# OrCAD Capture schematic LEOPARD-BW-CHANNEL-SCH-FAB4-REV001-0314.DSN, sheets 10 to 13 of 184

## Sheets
10 169_P1V05_PCH_TPS53318: size C; title: P1V05_PCH_TPS53318
11 168_PVCCIO_TPS53511: size A3; title: PVCCIO_TPS53511
12 167_PVPP_GH_TPS53318: size A3; title: PVPP_GH_TPS53318
13 166_PVDDQ_GH_Decoupling: size A3; title: PVDDQ_GH_DECOUPLING

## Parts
sheet 166_PVDDQ_GH_Decoupling
PC675  SCD1U25V3KX-GP  [C603H36]
PC676  SC1U25V3KX-GP  [C603H36]
PC677  SCD1U25V5KX-1GP  [C805H54]
PC678  SE470UF2VDM-GP  [CT7343H83]
PC679  SE470UF2VDM-GP  [CT7343H83]
PC680  SE470UF2VDM-GP  [CT7343H83]
PC681  SE470UF2VDM-GP  [CT7343H83]
PC682  SC47U4V5MX-2-GP  [C805H58]
PC683  SC47U4V5MX-2-GP  [C805H58]
PC684  SC47U4V5MX-2-GP  [C805H58]
PC685  SC47U4V5MX-2-GP  [C805H58]
PC686  SC22U6D3V5MX-5-GP  [C805H56]
PC687  SC22U6D3V5MX-5-GP  [C805H56]
PC688  SC22U6D3V5MX-5-GP  [C805H56]
PC689  SC22U6D3V5MX-5-GP  [C805H56]
PC690  SC22U6D3V5MX-5-GP  [C805H56]
PC691  SC22U6D3V5MX-5-GP  [C805H56]
PC692  SC22U6D3V5MX-5-GP  [C805H56]
PC693  SC22U6D3V5MX-5-GP  [C805H56]
PC694  SC22U6D3V5MX-5-GP  [C805H56]
PC695  SC22U6D3V5MX-5-GP  [C805H56]
PC696  SC22U6D3V5MX-5-GP  [C805H56]
PC697  SC22U6D3V5MX-5-GP  [C805H56]
PC698  SC22U6D3V5MX-5-GP  [C805H56]
PC699  SC22U6D3V5MX-5-GP  [C805H56]
PC700  SC22U6D3V5MX-5-GP  [C805H56]
PC701  SC22U6D3V5MX-5-GP  [C805H56]
PC702  SC22U6D3V5MX-5-GP  [C805H56]
PC703  SC22U6D3V5MX-5-GP  [C805H56]
PC704  SC22U6D3V5MX-5-GP  [C805H56]
PC705  SC22U6D3V5MX-5-GP  [C805H56]
PC706  SC22U6D3V5MX-5-GP  [C805H56]
PC707  SC22U6D3V5MX-5-GP  [C805H56]
PC708  SC22U6D3V5MX-5-GP  [C805H56]
PC709  SC22U6D3V5MX-5-GP  [C805H56]
PC710  SC22U6D3V5MX-5-GP  [C805H56]
PC711  SC22U6D3V5MX-5-GP  [C805H56]
PC712  SC22U6D3V5MX-5-GP  [C805H56]
PC713  SC22U6D3V5MX-5-GP  [C805H56]
PC714  SC22U6D3V5MX-5-GP  [C805H56]
PC715  SC22U6D3V5MX-5-GP  [C805H56]
PC716  SC22U6D3V5MX-5-GP  [C805H56]
PC717  SC22U6D3V5MX-5-GP  [C805H56]
PC718  SC22U6D3V5MX-5-GP  [C805H56]
PC719  SC22U6D3V5MX-5-GP  [C805H56]
PC720  SC22U6D3V5MX-5-GP  [C805H56]
PC721  SC22U6D3V5MX-5-GP  [C805H56]
PC722  SC22U6D3V5MX-5-GP  [C805H56]
PC723  SC22U6D3V5MX-5-GP  [C805H56]
PC724  SC22U6D3V5MX-5-GP  [C805H56]
PC725  SC22U6D3V5MX-5-GP  [C805H56]
PC865  SC22U6D3V5MX-5-GP  [C805H56]
PC866  SC22U6D3V5MX-5-GP  [C805H56]
PC867  SC22U6D3V5MX-5-GP  [C805H56]
PC868  SC22U6D3V5MX-5-GP  [C805H56]
PC869  SC22U6D3V5MX-5-GP  [C805H56]
PC870  SC22U6D3V5MX-5-GP  [C805H56]
PC871  SC22U6D3V5MX-5-GP  [C805H56]
PC872  SC22U6D3V5MX-5-GP  [C805H56]
PC1003  SC22U6D3V5MX-5-GP  [C805H56]
PC1004  SC22U6D3V5MX-5-GP  [C805H56]
PC1005  SC22U6D3V5MX-5-GP  [C805H56]
PL46  IND-65NH-GP  [L4038-1412H158]
PR403  33R3F-L-GP  [R603H22]
PR404  0R2F-L-GP  [R402H16]
PR405  0R2F-L-GP  [R402H16]
PTC8  E270U16VM-28-GP  [ECAP-100D6D3H363]
sheet 167_PVPP_GH_TPS53318
PC726  SC10U16V5KX-1-GP  [C805H54]
PC727  SC10U16V5KX-1-GP  [C805H54]
PC728  SC10U16V5KX-1-GP  [C805H54]
PC729  SC10U16V5KX-1-GP  [C805H54]
PC730  SCD1U16V3KX-3GP  [C603H36]
PC731  SC4D7U25V5KX-1-GP  [C805H58]
PC732  SCD1U50V3KX-GP  [C603H36]
PC733  SC2K2P50V3KX-GP  [C603]
PC734  SCD1U16V2KX-3GP  [C402H22]
PC735  SC1U10V2KX-4-GP  [C402H22]
PC736  SC1KP50V2KX-1GP  [C402H22]
PC737  SCD1U16V3KX-3GP  [C603H36]
PC738  SC22U6D3V5MX-5-GP  [C805H56]
PC739  SC47U4V5MX-2-GP  [C805H58]
PC740  SC47U4V5MX-2-GP  [C805H58]
PC741  SC47U4V5MX-2-GP  [C805H58]
PC742  SC47U4V5MX-2-GP  [C805H58]
PC743  SC47U4V5MX-2-GP  [C805H58]
PC744  SC47U4V5MX-2-GP  [C805H58]
PC1047  SC1U10V2KX-4-GP  [C402H22]
PD25  BZT52-C3V3S-GP  [SOD323AKH38]
PL35  BLM21PG220SN1DGP  [L20125H42]
PL36  IND-2D2UH-242-GP  [L7165-1732H119]
PR406  2D2R3-1-U-GP  [R603H22]
PR407  3D01R5F-GP  [R805H24]
PR409  0R2J-2-GP  [R402H16]
PR410  10R3F-GP  [R603H22]
PR411  3K9R2F-GP  [R402H16]
PR412  100KR2F-L1-GP  [R402H16]
PR413  3D01R5F-GP  [R805H24]
PR414  100KR2F-L1-GP  [R402H16]
PR415  100KR2F-L1-GP  [R402H16]
PR416  866KR2F-GP  [R402H16]
PR417  31K6R2F-GP  [R402H16]
PR418  619KR2F-GP  [R402H16]
PR419  10KR2F-2-GP  [R402H16]
PR420  0R3J-0-U-GP  [R603H22]
PR646  10KR2F-2-GP  [R402H16]
PR804  0R2J-2-GP  [R402H16]
PU36  TPS53318DQPR-GP  [DFN22G6050-G6133H60]
sheet 168_PVCCIO_TPS53511
PC745  SC1U16V3KX-5GP  [C603H36]
PC746  SC10U16V5KX-1-GP  [C805H54]
PC747  SCD1U16V2KX-3GP  [C402H22]
PC748  SC10U16V5KX-1-GP  [C805H54]
PC749  SCD1U50V3KX-GP  [C603H36]
PC750  SC3300P50V2KX-1GP  [C402H22]
PC751  SC1U16V3KX-5GP  [C603H36]
PC752  SCD1U50V3KX-GP  [C603H36]
PC753  SC22U6D3V5MX-5-GP  [C805H56]
PC754  SC22U6D3V5MX-5-GP  [C805H56]
PC755  SC22U6D3V5MX-5-GP  [C805H56]
PC756  SC1KP50V2KX-1GP  [C402H22]
PC1051  SC1KP50V2KX-1GP  [C402H22]
PC1052  SC2K2P50V3KX-GP  [C603]
PD1  PTZ2D4-GP  [D502715AKH87]
PG45  GAP-CLOSE-PWR-4-GP  [GAP-CLOSE-PWR-4]
PG46  COPPER-CLOSE-GP-U  [CON2C-U]
PL37  IND-4D7UH-185-GP-U  [L6965-1632-UH119]
PQ11  2N7002-7F-GP  [SOT23DGS2D4H44]
PR421  2D2R3-1-U-GP  [R603H22]
PR422  0R6J-3-GP  [R1206H28]
PR423  10KR2F-2-GP  [R402H16]
PR424  2K43R2F-GP  [R402H16]
PR425  10R3F-GP  [R603H22]
PR426  0R2J-2-GP  [R402H16]
PR427  6K65R2F-GP  [R402H16]
PR428  2KR2F-ML-GP  [R402H16]
PR429  10KR2F-2-GP  [R402H16]
PR430  18K7R2F-GP  [R402H16]
PR432  0R2J-2-GP  [R402H16]
PR433  10KR2F-2-GP  [R402H16]
PR434  2K2R2F-GP  [R402H16]
PR570  0R2J-2-GP  [R402H16]
PR805  0R2J-2-GP  [R402H16]
PR806  3D01R5F-GP  [R805H24]
PU37  TPS53511RGTR-GP  [QFN16G3-G1D7H40]
sheet 169_P1V05_PCH_TPS53318
PC11  SC22U6D3V5MX-5-GP  [C805H56]
PC486  SC470P50V2KX-3GP  [C402H22]
PC757  SC10U16V5KX-1-GP  [C805H54]
PC758  SC10U16V5KX-1-GP  [C805H54]
PC759  SC10U16V5KX-1-GP  [C805H54]
PC760  SC1U25V3KX-GP  [C603H36]
PC762  SCD1U16V2KX-3GP  [C402H22]
PC767  SCD1U50V3KX-GP  [C603H36]
PC768  SCD1U25V3KX-GP  [C603H36]
PC769  SC2K2P50V3KX-GP  [C603]
PC1015  SC4D7U25V5KX-1-GP  [C805H58]
PC1016  SC1U16V3KX-5GP  [C603H36]
PC1054  SC1U10V2KX-4-GP  [C402H22]
PD2  PTZ2D4-GP  [D502715AKH87]
PG69  COPPER-CLOSE-GP-U  [CON2C-U]
PL38  BLM21PG220SN1DGP  [L20125H42]
PL39  IND-D68UH-37-GP-U  [L7166-1830-UH197]
PR334  20KR2F-L-GP  [R402H16]
PR435  0R3J-0-U-GP  [R603H22]
PR436  10KR2F-2-GP  [R402H16]
PR437  10KR2F-2-GP  [R402H16]
PR438  0R2J-2-GP  [R402H16]
PR439  10KR2F-2-GP  [R402H16]
PR440  3D01R5F-GP  [R805H24]
PR444  7K32R2B-GP  [R402H16]
PR447  10KR2B-GP  [R402H16]
PR528  0R2J-2-GP  [R402H16]
PR529  10R3F-GP  [R603H22]
PR530  100KR2F-L1-GP  [R402H16]
PR532  475KR2F-GP  [R402H16]
PR533  309KR2F-GP  [R402H16]
PR536  2D2R3-1-U-GP  [R603H22]
PR537  88K7R2F-GP  [R402H16]
PR542  619KR2F-GP  [R402H16]
PR2167  0R2F-L-GP  [R402H16]
PR2168  100R2F-L1-GP-U  [R402H14]
PR2169  0R2F-L-GP  [R402H16]
PR2170  100R2F-L1-GP-U  [R402H14]
PTC9  SC22U6D3V5MX-5-GP  [C805H56]
PTC10  SC22U6D3V5MX-5-GP  [C805H56]
PTC12  SC22U6D3V5MX-5-GP  [C805H56]
PTC13  ST470U2D5VDM-13-GP  [CT7343H83]
PTC14  ST470U2D5VDM-13-GP  [CT7343H83]
PU53  TPS53318DQPR-GP  [DFN22G6050-G6133H60]

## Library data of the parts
PC675 PC768 = SCD1U25V3KX-GP: CHIP CAP C 0.1U 25V K0603 X7R; CATEGORIES: CAP_1.xV; GREENDFACTOR: R2_SA;HF_SA;G_SA;; MAIN_SOURCE: M; Package Type: RCL_GP; Part Number: 78.10422.2BL; SPEC: http://wpqssvr.wistron.com.tw:7001/wpqs/servlet/COM.qpart.Attachment?PartNumber=78.10422.2BL
PC676 PC760 = SC1U25V3KX-GP: CHIP CAP C 1U 25V K0603 X7R; GREENDFACTOR: R2_SA;HF_SA;G_SA;; Package Type: SMD-BCG; Part Number: 78.10522.2BL; SPEC: http://wpqssvr.wistron.com.tw:7001/wpqs/servlet/COM.qpart.Attachment?PartNumber=78.10522.2BL
PC677 = SCD1U25V5KX-1GP: CHIP CAP0.1U25V K0805 X7R(ROHS; GREENDFACTOR: R2_SA;HF_SA;G_SA;; Package Type: SMD-BCG; Part Number: 78.10422.21L; SPEC: http://wpqssvr.wistron.com.tw:7001/wpqs/servlet/COM.qpart.Attachment?PartNumber=78.10422.21L
PC678-PC681 = SE470UF2VDM-GP: CHIP CAP 470UF 2V EEFSX0D471X; GREENDFACTOR: R_SA;; Module: VR_DDR_P1V5_VDDQ; Package Type: SMD-TCG1; Part Number: 79.47719.2BL; Part Type: SMD-TCG1; Part_Function: Cout_bulk; Part_Spec: 470uF/2V/6mohm; Part_Type: Solid_al_cap; SPEC: http://wpqssvr.wistron.com.tw:7001/wpqs/servlet/COM.qpart.Attachment?PartNumber=79.47719.2BL; VENDOR_PN: EEFSX0D471XE
PC682-PC685 PC739-PC744 = SC47U4V5MX-2-GP: CHIP CAP C 47U 4V M0805 X6S; GREENDFACTOR: R2_SA;HF_SA;G_SA;; Package Type: SMD-BCG3; Part Number: 78.4761T.81L; SPEC: http://wpqssvr.wistron.com.tw:7001/wpqs/servlet/COM.qpart.Attachment?PartNumber=78.4761T.81L
PC11 PC686-PC725 PC738 PC753-PC755 PC865-PC872 PTC9 PTC10 PTC12 = SC22U6D3V5MX-5-GP: CHIP CAP C 22U 6.3V M0805 X6S; GREENDFACTOR: R2_SA;HF_SA;G_SA;; Package Type: SMD-BCG2; Part Number: 78.22610.81L; SPEC: http://wpqssvr.wistron.com.tw:7001/wpqs/servlet/COM.qpart.Attachment?PartNumber=78.22610.81L
PC1003-PC1005 = SC22U6D3V5MX-5-GP: CHIP CAP C 22U 6.3V M0805 X6S; GREENDFACTOR: R2_SA;HF_SA;G_SA;; Package Type: SMD-BCG2; Part Number: 78.22610.81L; SPEC: http://wpqssvr.wistron.com.tw:7001/wpqs/servlet/COM.qpart.Attachment?PartNumber=78.22610.81L; Size: 0805; Type: X6S
PL46 = IND-65NH-GP: CHIP IND 65NH FP0404R1-R065-R; GREENDFACTOR: R2_SA;; Part Number: 68.650CN.101; Part Type: DISCRET-G6; SPEC: http://wpqssvr.wistron.com.tw:7001/wpqs/servlet/COM.qpart.Attachment?PartNumber=68.650CN.101
PR403 = 33R3F-L-GP: CHIP RES 33 F 1/10W 0603; GREENDFACTOR: R2_SA;HF_SA;G_SA;; Package Type: SMD-RG; Part Number: 64.33R05.55L; SPEC: http://wpqssvr.wistron.com.tw:7001/wpqs/servlet/COM.qpart.Attachment?PartNumber=64.33R05.55L
PR404 PR405 PR2167 PR2169 = 0R2F-L-GP: CHIP RES 0 F 0402 RK73Z1ETTP KOA; GREENDFACTOR: R2_SA;; Package Type: SMD-RG5; Part Number: 64.R0005.L0L; SPEC: http://wpqssvr.wistron.com.tw:7001/wpqs/servlet/COM.qpart.Attachment?PartNumber=64.R0005.L0L
PTC8 = E270U16VM-28-GP: CAP EL 270U 16V RT2.5 6.3*8 SOLID CAP; GREENDFACTOR: R2_SA;HF_SA;; Part Number: 09.2771D.E4L; Part Spec: 270uF/16V/10mohm/5A; Part Type: DIP-TCG4; SPEC: http://wpqssvr.wistron.com.tw:7001/wpqs/servlet/COM.qpart.Attachment?PartNumber=09.2771D.E4L
PC726-PC729 PC746 PC748 PC757-PC759 = SC10U16V5KX-1-GP: CHIP CAP C 10U 16V K0805 X6S; GREENDFACTOR: R2_SA;; Package Type: SMD-BCG5; Part Number: 78.10621.81L; SPEC: http://wpqssvr.wistron.com.tw:7001/wpqs/servlet/COM.qpart.Attachment?PartNumber=78.10621.81L
PC730 PC737 = SCD1U16V3KX-3GP: CHIP CAP 0.1U16V K0603 X7R(ROH; GREENDFACTOR: R2_SA;R_SA;HF_SA;G_SA;; Module: VR_SYSTEM_P1V8; Package Type: SMD-BCG; Part Number: 78.10421.2BL; SPEC: http://wpqssvr.wistron.com.tw:7001/wpqs/servlet/COM.qpart.Attachment?PartNumber=78.10421.2BL; Size: 0603; Type: X7R
PC731 PC1015 = SC4D7U25V5KX-1-GP: CHIP CAP C 4.7U 25V K0805 X7R; GREENDFACTOR: R2_SA;HF_SA;G_SA;; Package Type: SMD-BCG4; Part Number: 078.47522.0211; SPEC: http://wpqssvr.wistron.com.tw:7001/wpqs/servlet/COM.qpart.Attachment?PartNumber=078.47522.0211
PC732 PC749 PC767 = SCD1U50V3KX-GP: CHIP CAP C 0.1U 50V K0603 X7R; GREENDFACTOR: R2_SA;HF_SA;G_SA;; Level: SMD; MAIN_SOURCE: M; Package Type: RCL_GP; Part Number: 78.10424.2BL; Part Type: RCL_GP; SPEC: http://wpqssvr.wistron.com.tw:7001/wpqs/servlet/COM.qpart.Attachment?PartNumber=78.10424.2BL; Status: POP
PC733 PC1052 = SC2K2P50V3KX-GP: CHIP CAP C 2200P 50V K0603 X7R; GREENDFACTOR: R2_SA;HF_SA;G_SA;; Level: SMD; POP?: NOPOP; Package Type: SMD-BCG6; Part Number: 78.22224.2BL; Part Type: SMD-BCG6; SPEC: http://wpqssvr.wistron.com.tw:7001/wpqs/servlet/COM.qpart.Attachment?PartNumber=78.22224.2BL; Status: POP
PC734 = SCD1U16V2KX-3GP: CHIP CAP C 0.1U 16V K0402 X7R; CATEGORIES: CAP_1.xV; GREENDFACTOR: R2_SA;HF_SA;G_SA;; MAIN_SOURCE: M; Part Number: 78.10421.2FL; Part Type: SMD-BCG; SPEC: http://wpqssvr.wistron.com.tw:7001/wpqs/servlet/COM.qpart.Attachment?PartNumber=78.10421.2FL
PC735 = SC1U10V2KX-4-GP: CHIP CAP C 1U 10V K 0402 X6S; GREENDFACTOR: R2_SA;HF_SA;; Package Type: SMD-BCG6; Part Number: 78.10523.8FL; SPEC: http://wpqssvr.wistron.com.tw:7001/wpqs/servlet/COM.qpart.Attachment?PartNumber=78.10523.8FL
PC736 = SC1KP50V2KX-1GP: CHIP CAP 1000P50V K0402 X7R(RO; GREENDFACTOR: R2_SA;HF_SA;G_SA;; Level: SMD; MAIN_SOURCE: M; Package Type: SMD-BCG; Part Number: 78.10224.2FL; Part Type: SMD-BCG; SPEC: http://wpqssvr.wistron.com.tw:7001/wpqs/servlet/COM.qpart.Attachment?PartNumber=78.10224.2FL; Status: POP
PC1047 PC1054 = SC1U10V2KX-4-GP: CHIP CAP C 1U 10V K 0402 X6S; GREENDFACTOR: R2_SA;HF_SA;; POP?: NOPOP; Package Type: SMD-BCG6; Part Number: 78.10523.8FL; SPEC: http://wpqssvr.wistron.com.tw:7001/wpqs/servlet/COM.qpart.Attachment?PartNumber=78.10523.8FL
PD25 = BZT52-C3V3S-GP: DIODE ZEN BZT52-C3V3S 3.3V SOD-323; GREENDFACTOR: R2_SA;; Part Number: 83.3R303.G3F; Part Type: DISCRET-G4; SPEC: http://wpqssvr.wistron.com.tw:7001/wpqs/servlet/COM.qpart.Attachment?PartNumber=83.3R303.G3F
PL35 PL38 = BLM21PG220SN1DGP: CHIP BEAD BLM21PG220SN1D (LF); GREENDFACTOR: R2_SA;HF_SA;; Level: SMD; Package Type: DISCRET-G; Part Number: 68.00084.831; Part Type: DISCRET-G; SPEC: http://wpqssvr.wistron.com.tw:7001/wpqs/servlet/COM.qpart.Attachment?PartNumber=68.00084.831; Status: POP
PL36 = IND-2D2UH-242-GP: CHIP IND 2.2UH M SPM6530T-2R2M; GREENDFACTOR: R2_SA;HF_SA;; Package Type: DISCRET-G6; Part Number: 68.2R21E.10X; SPEC: http://wpqssvr.wistron.com.tw:7001/wpqs/servlet/COM.qpart.Attachment?PartNumber=68.2R21E.10X
PR406 PR421 PR536 = 2D2R3-1-U-GP: CHIP RES 2.2 F 1/10W 0603(ROHS; GREENDFACTOR: R2_SA;HF_SA;G_SA;; Package Type: RCL_GP; Part Number: 64.2R205.55L; SPEC: http://wpqssvr.wistron.com.tw:7001/wpqs/servlet/COM.qpart.Attachment?PartNumber=64.2R205.55L
PR407 = 3D01R5F-GP: CHIP RES 3.01 F 1/8W 0805; GREENDFACTOR: R2_SA;HF_SA;G_SA;; Level: SMD; Package Type: SMD-RG5; Part Number: 64.3R015.16L; Part Type: SMD-RG5; SPEC: http://wpqssvr.wistron.com.tw:7001/wpqs/servlet/COM.qpart.Attachment?PartNumber=64.3R015.16L; Status: POP
PR409 PR426 PR432 PR570 PR804 PR805 = 0R2J-2-GP: CHIP RES 0 J 1/16W 0402; GREENDFACTOR: R2_SA;HF_SA;G_SA;; Level: SMD; Package Type: SMD-RG; Part Number: 63.R0034.1DL; Part Type: SMD-RG; ROOM: VR_CHIPSET; SPEC: http://wpqssvr.wistron.com.tw:7001/wpqs/servlet/COM.qpart.Attachment?PartNumber=63.R0034.1DL; Status: POP
PR410 PR425 PR529 = 10R3F-GP: CHIP RES 10 F 1/10W 0603; GREENDFACTOR: R2_SA;HF_SA;G_SA;; Level: SMD; Package Type: RCL_GP; Part Number: 64.10R05.55L; Part Type: RCL_GP; SPEC: http://wpqssvr.wistron.com.tw:7001/wpqs/servlet/COM.qpart.Attachment?PartNumber=64.10R05.55L; Status: POP
PR411 = 3K9R2F-GP: CHIP RES 3.9K F 1/16W 0402; GREENDFACTOR: R2_SA;HF_SA;G_SA;; Package Type: RCL_GP; Part Number: 64.39015.6DL; SPEC: http://wpqssvr.wistron.com.tw:7001/wpqs/servlet/COM.qpart.Attachment?PartNumber=64.39015.6DL
PR412 = 100KR2F-L1-GP: CHIP RES 100K F 1/16W 0402; GREENDFACTOR: R2_SA;HF_SA;G_SA;; Part Number: 64.10035.6DL; Part Type: SMD-RG; SPEC: http://wpqssvr.wistron.com.tw:7001/wpqs/servlet/COM.qpart.Attachment?PartNumber=64.10035.6DL
PR413 PR806 = 3D01R5F-GP: CHIP RES 3.01 F 1/8W 0805; GREENDFACTOR: R2_SA;HF_SA;G_SA;; Level: SMD; POP?: NOPOP; Package Type: SMD-RG5; Part Number: 64.3R015.16L; Part Type: SMD-RG5; SPEC: http://wpqssvr.wistron.com.tw:7001/wpqs/servlet/COM.qpart.Attachment?PartNumber=64.3R015.16L; Status: POP
PR414 PR530 = 100KR2F-L1-GP: CHIP RES 100K F 1/16W 0402; GREENDFACTOR: R2_SA;HF_SA;G_SA;; Level: SMD; POP?: NOPOP; Package Type: SMD-RG; Part Number: 64.10035.6DL; Part Type: SMD-RG; SPEC: http://wpqssvr.wistron.com.tw:7001/wpqs/servlet/COM.qpart.Attachment?PartNumber=64.10035.6DL; Status: NOPOP
PR415 = 100KR2F-L1-GP: CHIP RES 100K F 1/16W 0402; GREENDFACTOR: R2_SA;HF_SA;G_SA;; Package Type: SMD-RG; Part Number: 64.10035.6DL; SPEC: http://wpqssvr.wistron.com.tw:7001/wpqs/servlet/COM.qpart.Attachment?PartNumber=64.10035.6DL
PR416 = 866KR2F-GP: CHP RES 866K F 1/16W 0402; GREENDFACTOR: R2_SA;HF_SA;G_SA;; Level: SMD; POP?: NOPOP; Package Type: SMD-RG4; Part Number: 64.86635.6DL; Part Type: SMD-RG4; SPEC: http://wpqssvr.wistron.com.tw:7001/wpqs/servlet/COM.qpart.Attachment?PartNumber=64.86635.6DL; Status: POP
PR417 = 31K6R2F-GP: CHIP RES 31.6K F 1/16W 0402; GREENDFACTOR: R2_SA;HF_SA;G_SA;; Package Type: RCL_GP; Part Number: 64.31625.6DL; SPEC: http://wpqssvr.wistron.com.tw:7001/wpqs/servlet/COM.qpart.Attachment?PartNumber=64.31625.6DL
PR418 PR542 = 619KR2F-GP: CHIP RES 619K F 1/16W 0402; GREENDFACTOR: R2_SA;HF_SA;G_SA;; Level: SMD; POP?: NOPOP; Package Type: SMD-RG3; Part Number: 64.61935.6DL; Part Type: SMD-RG3; SPEC: http://wpqssvr.wistron.com.tw:7001/wpqs/servlet/COM.qpart.Attachment?PartNumber=64.61935.6DL; Status: NOPOP
PR419 = 10KR2F-2-GP: CHIP RES 10K F 1/16W 0402; GREENDFACTOR: R2_SA;HF_SA;G_SA;; Package Type: SMD-RG; Part Number: 64.10025.6DL; SPEC: http://wpqssvr.wistron.com.tw:7001/wpqs/servlet/COM.qpart.Attachment?PartNumber=64.10025.6DL
PR420 PR435 = 0R3J-0-U-GP: CHIP RES 0 J 1/10W 0603; GREENDFACTOR: R2_SA;HF_SA;G_SA;; Package Type: RCL_GP; Part Number: 63.00000.00L; SPEC: http://wpqssvr.wistron.com.tw:7001/wpqs/servlet/COM.qpart.Attachment?PartNumber=63.00000.00L
PR437 PR439 PR646 = 10KR2F-2-GP: CHIP RES 10K F 1/16W 0402; GREENDFACTOR: R2_SA;HF_SA;G_SA;; Level: SMD; Package Type: SMD-RG; Part Number: 64.10025.6DL; Part Type: SMD-RG; SPEC: http://wpqssvr.wistron.com.tw:7001/wpqs/servlet/COM.qpart.Attachment?PartNumber=64.10025.6DL
PU36 PU53 = TPS53318DQPR-GP: IC PWR CTRL TPS53318DQPR QFN 22P; GREENDFACTOR: R2_C;HF_C;; Package Type: DISCRET-G5; Part Number: 74.53318.073; SPEC: http://wpqssvr.wistron.com.tw:7001/wpqs/servlet/COM.qpart.Attachment?PartNumber=74.53318.073
PC745 PC751 = SC1U16V3KX-5GP: CHIP CAP C 1U 16V K0603 X7R; GREENDFACTOR: R2_SA;HF_SA;G_SA;; MAIN_SOURCE: M; Package Type: SMD-BCG3; Part Number: 78.10521.2BL; SPEC: http://wpqssvr.wistron.com.tw:7001/wpqs/servlet/COM.qpart.Attachment?PartNumber=78.10521.2BL
PC747 = SCD1U16V2KX-3GP: CHIP CAP C 0.1U 16V K0402 X7R; GREENDFACTOR: R2_SA;HF_SA;G_SA;; MAIN_SOURCE: M; Package Type: SMD-BCG; Part Number: 78.10421.2FL; SPEC: http://wpqssvr.wistron.com.tw:7001/wpqs/servlet/COM.qpart.Attachment?PartNumber=78.10421.2FL
PC750 = SC3300P50V2KX-1GP: CHIP CAP C 3300P 50V K0402 X7R; GREENDFACTOR: R2_SA;HF_SA;G_SA;; MAIN_SOURCE: M; Package Type: SMD-BCG; Part Number: 78.33224.2FL; SPEC: http://wpqssvr.wistron.com.tw:7001/wpqs/servlet/COM.qpart.Attachment?PartNumber=78.33224.2FL
PC752 = SCD1U50V3KX-GP: CHIP CAP C 0.1U 50V K0603 X7R; GREENDFACTOR: R2_SA;HF_SA;G_SA;; Level: SMD; MAIN_SOURCE: M; POP?: NOPOP; Package Type: RCL_GP; Part Number: 78.10424.2BL; Part Type: RCL_GP; SPEC: http://wpqssvr.wistron.com.tw:7001/wpqs/servlet/COM.qpart.Attachment?PartNumber=78.10424.2BL
PC756 = SC1KP50V2KX-1GP: CHIP CAP 1000P50V K0402 X7R(RO; GREENDFACTOR: R2_SA;HF_SA;G_SA;; Level: SMD; MAIN_SOURCE: M; POP?: NOPOP; Package Type: SMD-BCG; Part Number: 78.10224.2FL; Part Type: SMD-BCG; SPEC: http://wpqssvr.wistron.com.tw:7001/wpqs/servlet/COM.qpart.Attachment?PartNumber=78.10224.2FL
PC1051 = SC1KP50V2KX-1GP: CHIP CAP C 1000P 50V K0402 X7R; CATEGORIES: CAP_Small; GREENDFACTOR: R2_SA;HF_SA;G_SA;; MAIN_SOURCE: M; Part Number: 78.10224.2FL; Part Type: SMD-BCG; SPEC: http://wpqssvr.wistron.com.tw:7001/wpqs/servlet/COM.qpart.Attachment?PartNumber=78.10224.2FL
PD1 = PTZ2D4-GP: DIODE ZEN PTZ2.4B 2.4V PMDS; GREENDFACTOR: R2_SA;; Package Type: DISCRET-G7; Part Number: 83.2R403.F3H; SPEC: http://wpqssvr.wistron.com.tw:7001/wpqs/servlet/COM.qpart.Attachment?PartNumber=83.2R403.F3H
PG45 = GAP-CLOSE-PWR-4-GP: PAD FOR COPPER-CLOSE; GREENDFACTOR: R2_C;; Package Type: DISCRET-G7; Part Number: ZZ.C0N2C.011; SPEC: http://wpqssvr.wistron.com.tw:7001/wpqs/servlet/COM.qpart.Attachment?PartNumber=ZZ.C0N2C.011
PG46 PG69 = COPPER-CLOSE-GP-U: COPPER CLOSE; GREENDFACTOR: Regular;; Level: SMD; Package Type: DISCRET-G9; Part Number: ZZ.CON2C.XXX; Part Type: DISCRET-G9; SPEC: http://wpqssvr.wistron.com.tw:7001/wpqs/servlet/COM.qpart.Attachment?PartNumber=ZZ.CON2C.XXX
PL37 = IND-4D7UH-185-GP-U: CHIP IND 4.7UH SPM6530T-4R7M; Alternate: 68.4R710.20R; GREENDFACTOR: R2_SA;HF_SA;; Level: SMD; Package Type: DISCRET-G9; Part Number: 68.4R71C.10U; SPEC: http://wpqssvr.wistron.com.tw:7001/wpqs/servlet/COM.qpart.Attachment?PartNumber=68.4R71C.10U; Status: POP
PQ11 = 2N7002-7F-GP: FET MOS 2N7002-7-F NC SOT-23; GREENDFACTOR: R2_SA;HF_SA;G_SA;; Package Type: DISCRET-G; Part Number: 84.27002.N31; SPEC: http://wpqssvr.wistron.com.tw:7001/wpqs/servlet/COM.qpart.Attachment?PartNumber=84.27002.N31
PR422 = 0R6J-3-GP: CHIP RES 0 J 1/4W 1206 (ROHS); GREENDFACTOR: R2_SA;HF_SA;G_SA;; Level: SMD; Package Type: SMD-RG; Part Number: 63.R0032.11L; Part Type: SMD-RG; SPEC: http://wpqssvr.wistron.com.tw:7001/wpqs/servlet/COM.qpart.Attachment?PartNumber=63.R0032.11L; Status: POP
PR423 = 10KR2F-2-GP: CHIP RES 10K F 1/16W 0402; GREENDFACTOR: R2_SA;HF_SA;G_SA;; Level: SMD; Package Type: SMD-RG; Part Number: 64.10025.6DL; Part Type: SMD-RG; SPEC: http://wpqssvr.wistron.com.tw:7001/wpqs/servlet/COM.qpart.Attachment?PartNumber=64.10025.6DL; Status: POP
PR424 = 2K43R2F-GP: CHIP RES 2.43K F 1/16W 0402; GREENDFACTOR: R2_SA;HF_SA;G_SA;; Package Type: RCL_GP; Part Number: 64.24315.6DL; SPEC: http://wpqssvr.wistron.com.tw:7001/wpqs/servlet/COM.qpart.Attachment?PartNumber=64.24315.6DL
PR427 = 6K65R2F-GP: CHIP RES 6.65K F 1/16W 0402; GREENDFACTOR: R2_SA;HF_SA;G_SA;; POP?: NOPOP; Package Type: RCL_GP; Part Number: 64.66515.6DL; SPEC: http://wpqssvr.wistron.com.tw:7001/wpqs/servlet/COM.qpart.Attachment?PartNumber=64.66515.6DL
PR428 = 2KR2F-ML-GP: CHIP RES 2K F 1/16W 0402; GREENDFACTOR: R2_SA;HF_SA;G_SA;; POP?: NOPOP; Package Type: SMD-RG1; Part Number: 64.20015.6DLML; SPEC: http://wpqssvr.wistron.com.tw:7001/wpqs/servlet/COM.qpart.Attachment?PartNumber=64.20015.6DLML
PR429 = 10KR2F-2-GP: CHIP RES 10K F 1/16W 0402; GREENDFACTOR: R2_SA;HF_SA;G_SA;; Level: SMD; POP?: NOPOP; Package Type: SMD-RG; Part Number: 64.10025.6DL; Part Type: SMD-RG; SPEC: http://wpqssvr.wistron.com.tw:7001/wpqs/servlet/COM.qpart.Attachment?PartNumber=64.10025.6DL; Status: POP
PR430 = 18K7R2F-GP: CHIP RES 18.7K F 1/16W 0402; GREENDFACTOR: R2_SA;HF_SA;G_SA;; Package Type: RCL_GP; Part Number: 64.18725.6DL; SPEC: http://wpqssvr.wistron.com.tw:7001/wpqs/servlet/COM.qpart.Attachment?PartNumber=64.18725.6DL
PR433 PR436 = 10KR2F-2-GP: CHIP RES 10K F 1/16W 0402; GREENDFACTOR: R2_SA;HF_SA;G_SA;; Level: SMD; POP?: NOPOP; Package Type: SMD-RG; Part Number: 64.10025.6DL; Part Type: SMD-RG; SPEC: http://wpqssvr.wistron.com.tw:7001/wpqs/servlet/COM.qpart.Attachment?PartNumber=64.10025.6DL
PR434 = 2K2R2J-2-GP: CHIP RES 2.2K F 1/16W 0402; Category: BMC; DESCRIPTIO: CHIP RES 2.2K J 1/16W 0402; GREENDFACTOR: R2_SA;HF_SA;G_SA;; Package Type: RCL_GP; Part Number: 64.22015.6DL; Part Type: RCL_GP; SPEC: http://wpqssvr.wistron.com.tw:7001/wpqs/servlet/COM.qpart.Attachment?PartNumber=64.22015.6DL; VENDORPARTNUMBER: RM04FTN2201/RTT022201FTH/RR0510S-222-FN/RC0402FR-072K2L
PU37 = TPS53511RGTR-GP: IC PWM CTRL TPS53511RGTR QFN 16P; GREENDFACTOR: R2_SA;; Part Number: 74.53511.073; Part Type: DISCRET-G9; SPEC: http://wpqssvr.wistron.com.tw:7001/wpqs/servlet/COM.qpart.Attachment?PartNumber=74.53511.073
PC486 = SC470P50V2KX-3GP: CHIP CAP 470P50V K0402 X7R(ROH; CATEGORIES: CAP_Small; GREENDFACTOR: R2_SA;HF_SA;G_SA;; MAIN_SOURCE: M; Package Type: SMD-BCG; Part Number: 78.47124.2FL; SPEC: http://wpqssvr.wistron.com.tw:7001/wpqs/servlet/COM.qpart.Attachment?PartNumber=78.47124.2FL
PC762 = SCD1U16V2KX-3GP: CHIP CAP C 0.1U 16V K0402 X7R; CATEGORIES: CAP_1.xV; GREENDFACTOR: R2_SA;HF_SA;G_SA;; MAIN_SOURCE: M; Module: BMC_VR; Package Type: SMD-BCG; Part Number: 78.10421.2FL; Part Type: SMD-BCG; SPEC: http://wpqssvr.wistron.com.tw:7001/wpqs/servlet/COM.qpart.Attachment?PartNumber=78.10421.2FL
PC769 = SC2K2P50V3KX-GP: CHIP CAP C 2200P 50V K0603 X7R; GREENDFACTOR: R2_SA;HF_SA;G_SA;; Level: SMD; POP?: NOPOP; Package Type: SMD-BCG6; Part Number: 78.22224.2BL; Part Type: SMD-BCG6; SPEC: http://wpqssvr.wistron.com.tw:7001/wpqs/servlet/COM.qpart.Attachment?PartNumber=78.22224.2BL
PC1016 = SC1U16V3KX-5GP: CHIP CAP C 1U 16V K0603 X7R; GREENDFACTOR: R2_SA;HF_SA;G_SA;; Level: SMD; MAIN_SOURCE: M; Package Type: SMD-BCG3; Part Number: 78.10521.2BL; SPEC: http://wpqssvr.wistron.com.tw:7001/wpqs/servlet/COM.qpart.Attachment?PartNumber=78.10521.2BL; Status: POP
PD2 = PTZ2D4-GP: DIODE ZEN PTZ2.4B 2.4V PMDS; GREENDFACTOR: R2_SA;; Module: PCH_VR; Package Type: DISCRET-G7; Part Number: 83.2R403.F3H; SPEC: http://wpqssvr.wistron.com.tw:7001/wpqs/servlet/COM.qpart.Attachment?PartNumber=83.2R403.F3H
PL39 = IND-D68UH-37-GP-U: CHIP CHOKE 0.68UH PCMB065T-R68; GREENDFACTOR: R2_SA;; Package Type: DISCRET-G6; Part Number: 68.R6810.20D; SPEC: http://wpqssvr.wistron.com.tw:7001/wpqs/servlet/COM.qpart.Attachment?PartNumber=68.R6810.20D
PR334 = 20KR2F-L-GP: CHIP RES 20K F 1/16W 0402; GREENDFACTOR: R2_SA;HF_SA;G_SA;; Part Number: 64.20025.6DL; Part Type: SMD-RG; SPEC: http://wpqssvr.wistron.com.tw:7001/wpqs/servlet/COM.qpart.Attachment?PartNumber=64.20025.6DL
PR438 PR528 = 0R2J-2-GP: CHIP RES 0 J 1/16W 0402; GREENDFACTOR: R2_SA;HF_SA;G_SA;; Level: SMD; Package Type: SMD-RG; Part Number: 63.R0034.1DL; Part Type: SMD-RG; ROOM: VR_CHIPSET; SPEC: http://wpqssvr.wistron.com.tw:7001/wpqs/servlet/COM.qpart.Attachment?PartNumber=63.R0034.1DL
PR440 = 3D01R5F-GP: CHIP RES 3.01 F 1/8W 0805; GREENDFACTOR: R2_SA;HF_SA;G_SA;; Level: SMD; POP?: NOPOP; Package Type: SMD-RG5; Part Number: 64.3R015.16L; Part Type: SMD-RG5; SPEC: http://wpqssvr.wistron.com.tw:7001/wpqs/servlet/COM.qpart.Attachment?PartNumber=64.3R015.16L
PR444 = 7K32R2B-GP: CHIP RES 7.32K B 1/16W 0402 TCR:50PPM; GREENDFACTOR: R2_SA;HF_SA;G_SA;; Package Type: SMD-RG4; Part Number: 64.7321D.6DL; SPEC: http://wpqssvr.wistron.com.tw:7001/wpqs/servlet/COM.qpart.Attachment?PartNumber=64.7321D.6DL
PR447 = 10KR2B-GP: CHIP RES 10K B 1/16W 0402; GREENDFACTOR: R2_SA;HF_SA;G_SA;; Part Number: 64.1002D.6DL; Part Type: SMD-RG3; SPEC: http://wpqssvr.wistron.com.tw:7001/wpqs/servlet/COM.qpart.Attachment?PartNumber=64.1002D.6DL
PR532 = 475KR2F-GP: CHIP RES 475K F 1/16W 0402; GREENDFACTOR: R2_SA;HF_SA;G_SA;; Level: SMD; Package Type: SMD-RG3; Part Number: 64.47535.6DL; Part Type: SMD-RG3; SPEC: http://wpqssvr.wistron.com.tw:7001/wpqs/servlet/COM.qpart.Attachment?PartNumber=64.47535.6DL
PR533 = 309KR2F-GP: CHIP RES 309K F 1/16W 0402; GREENDFACTOR: R2_SA;HF_SA;G_SA;; Package Type: SMD-RG; Part Number: 64.30935.6DL; SPEC: http://wpqssvr.wistron.com.tw:7001/wpqs/servlet/COM.qpart.Attachment?PartNumber=64.30935.6DL
PR537 = 88K7R2F-GP: CHIP RES 88.7K F 1/16W 0402; GREENDFACTOR: R2_SA;HF_SA;G_SA;; Part Number: 64.88725.6DL; Part Type: SMD-RG3; SPEC: http://wpqssvr.wistron.com.tw:7001/wpqs/servlet/COM.qpart.Attachment?PartNumber=64.88725.6DL
PR2168 PR2170 = 100R2F-L1-GP-U: CHIP RES 100 F 1/16W 0402; GREENDFACTOR: R2_SA;HF_SA;G_SA;; Package Type: SMD-RG; Part Number: 64.10005.6DL; SPEC: http://wpqssvr.wistron.com.tw:7001/wpqs/servlet/COM.qpart.Attachment?PartNumber=64.10005.6DL
PTC13 PTC14 = ST470U2D5VDM-13-GP: CHIP CAP EL 470U 2.5V M7343 ESR4.5 SX; GREENDFACTOR: R2_C;HF_C;; Module: VR_PVCORE_CPU; Package Type: SMD-TCG5; Part Number: 79.4771V.6AL; Part_Spec: 470uF/2.5V/4.5mohm; Quotation: 8_1; SPEC: http://wpqssvr.wistron.com.tw:7001/wpqs/servlet/COM.qpart.Attachment?PartNumber=79.4771V.6AL; VENDOR_PN: EEFSX0E471E4

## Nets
AGND_P1V05_PCH: PG69.1 PR528.2 PR530.1 PR537.1 PR542.1 PR2168.1
AGND_PVCCIO: PC750.2 PG46.1 PQ11.S PR423.1 PU37.4(GND)
AGND_PVPP_GH: PR414.1 PR415.1 PR418.1 PR419.2 PR420.1 PR804.2
GND: PC11.2 PC675.2 PC676.2 PC677.2 PC678.2 PC679.2 PC680.2 PC681.2 PC682.2 PC683.2 PC684.2 PC685.2 PC686.2 PC687.2 PC688.2 PC689.2 PC690.2 PC691.2 PC692.2 PC693.2 PC694.2 PC695.2 PC696.2 PC697.2 PC698.2 PC699.2 PC700.2 PC701.2 PC702.2 PC703.2 PC704.2 PC705.2 PC706.2 PC707.2 PC708.2 PC709.2 PC710.2 PC711.2 PC712.2 PC713.2 PC714.2 PC715.2 PC716.2 PC717.2 PC718.2 PC719.2 PC720.2 PC721.2 PC722.2 PC723.2 PC724.2 PC725.2 PC726.2 PC727.2 PC728.2 PC729.2 PC730.2 PC731.2 PC735.1 PC737.2 PC738.2 PC739.2 PC740.2 PC741.2 PC742.2 PC743.2 PC744.2 PC745.2 PC746.2 PC747.2 PC748.2 PC751.2 PC753.2 PC754.2 PC755.2 PC757.2 PC758.2 PC759.2 PC760.2 PC762.2 PC865.2 PC866.2 PC867.2 PC868.2 PC869.2 PC870.2 PC871.2 PC872.2 PC1003.2 PC1004.2 PC1005.2 PC1015.2 PC1016.1 PC1047.1 PC1054.1 PD1.A(ANODE) PD2.A(ANODE) PD25.A(ANODE) PG46.2 PG69.2 PR334.1 PR403.2 PR405.1 PR413.2 PR420.2 PR429.2 PR434.1 PR440.2 PR806.2 PR2169.1 PTC8.2 PTC9.2 PTC10.2 PTC12.2 PTC13.2 PTC14.2 PU36.23(GND) PU37.7(PGND) PU37.8(PGND) PU37.17(GND) PU53.23(GND) ; also on sheet 1 2 3 4 5 6 7 8 9 14 15 16 17 18 19 20 21 22 23 24 25 26 27 28 29 30 31 32 33 34 35 36 37 38 39 44 46 47 49 50 51 52 53 54 55 56 57 58 59 60 61 62 63 64 65 66 69 70 71 73 74 75 76 78 79 80 81 82 83 84 86 87 88 89 90 91 92 93 94 95 96 97 98 99 100 101 102 103 104 105 106 107 108 109 110 111 112 113 114 115 116 117 118 119 128 129 138 139 159 160 161 166 168 169 170 171 172 173 174 175 176 177 180 181 182 183 184
P1V05_PCH: PC11.1 PC768.1 PD2.K(CATHODE) PL39.2(S) PR2167.1 PR2170.2 PTC9.1 PTC10.1 PTC12.1 PTC13.1 PTC14.1 ; also on sheet 45 87 173 175
P1V05_PCH_EN: PC1054.2 PR436.1 PR438.2 PU53.2(EN)
P1V05_PCH_LL: PC767.2 PC769.1 PL39.1(F) PR439.1 PU53.6(LL#6) PU53.7(LL#7) PU53.8(LL#8) PU53.9(LL#9) PU53.10(LL#10) PU53.11(LL#11)
P1V05_PCH_LL_R: PC486.1 PC768.2 PR439.2
P1V05_PCH_MODE: PR530.2 PR532.1 PU53.20(MODE)
P1V05_PCH_REOMTEN: PR447.2 PR2168.2 PR2169.2
P1V05_PCH_REOMTEP: PR529.1 PR2167.2 PR2170.1
P1V05_PCH_RF: PR533.2 PR542.2 PU53.22(RF)
P1V05_PCH_ROVP: PR528.1 PU53.5(ROVP)
P1V05_PCH_SNB: PC769.2 PR440.1
P1V05_PCH_TRIP: PR537.2 PU53.21(TRIP)
P1V05_PCH_VBST: PR435.1 PU53.4(VBST)
P1V05_PCH_VBST_RC: PC767.1 PR435.2
P1V05_PCH_VDD: PC1015.1 PR536.2 PU53.19(VDD)
P1V05_PCH_VFB: PC486.2 PR444.1 PR447.1 PU53.1(VFB)
P1V05_PCH_VFB_R: PR444.2 PR529.2
P1V05_PCH_VIN: PC757.1 PC758.1 PC759.1 PC760.1 PC762.1 PL38.2 PU53.12(VIN) PU53.13(VIN) PU53.14(VIN) PU53.15(VIN) PU53.16(VIN) PU53.17(VIN)
P1V05_PCH_VREG: PC1016.2 PR437.2 PR533.1 PU53.18(VREG)
P3V3_STBY: PR433.1 PR436.2 PR646.1 ; also on sheet 2 3 5 6 8 9 15 16 17 20 21 22 25 26 27 30 31 33 34 35 37 38 39 45 47 49 50 51 52 54 55 59 60 61 62 63 64 65 66 69 70 71 72 73 74 76 79 83 84 87 88 89 90 91 92 93 94 95 96 97 98 99 159 161 166 168 173 174 176 177 179 180 182 183 184
P12V_STBY: PC675.1 PC676.1 PL35.1 PL38.1 PL46.1 PR406.1 PR421.2 PR422.2 PR536.1 ; also on sheet 2 3 4 7 9 17 18 22 23 27 28 32 36 59 60 75 95 104 105 106 107 108 109 110 111 112 113 114 115 116 117 118 119
PVCCIO: PC752.2 PC753.1 PC754.1 PC755.1 PD1.K(CATHODE) PG45.1 PL37.2 ; also on sheet 16 26 35 39 46 47 68 87 97 100 101 102 103 120 129 130 139 160 173 177 179 182
PVCCIO__SNB: PC1052.2 PR806.1
PVCCIO_CC: PG45.2 PR425.1
PVCCIO_CC_R: PC1051.1 PR424.1 PR425.2 PR426.2
PVCCIO_EN_R: PR432.1 PU37.6(EN)
PVCCIO_QS: PQ11.D PR430.2
PVCCIO_SS: PC750.1 PU37.3(SS)
PVCCIO_SW: PC749.1 PC1052.1 PL37.1 PR428.1 PU37.9(SW#9) PU37.10(SW#10) PU37.11(SW#11)
PVCCIO_VBST: PR805.2 PU37.12(VBST)
PVCCIO_VBST_RR: PC749.2 PR805.1
PVCCIO_VCC: PC745.1 PR421.1 PU37.15(VCC)
PVCCIO_VFB: PC756.2 PC1051.2 PR423.2 PR424.2 PR430.1 PU37.1(VFB)
PVCCIO_VFB_R: PC752.1 PC756.1 PR428.2
PVCCIO_VIN: PC746.1 PC747.1 PC748.1 PR422.1 PU37.13(VIN#13) PU37.14(VIN#14)
PVCCIO_VO: PR426.1 PU37.16(VO)
PVCCIO_VRG5: PC751.1 PR427.2 PU37.2(VREG5)
PVDDQ_GH: PC678.1 PC679.1 PC680.1 PC681.1 PC682.1 PC683.1 PC684.1 PC685.1 PC686.1 PC687.1 PC688.1 PC689.1 PC690.1 PC691.1 PC692.1 PC693.1 PC694.1 PC695.1 PC696.1 PC697.1 PC698.1 PC699.1 PC700.1 PC701.1 PC702.1 PC703.1 PC704.1 PC705.1 PC706.1 PC707.1 PC708.1 PC709.1 PC710.1 PC711.1 PC712.1 PC713.1 PC714.1 PC715.1 PC716.1 PC717.1 PC718.1 PC719.1 PC720.1 PC721.1 PC722.1 PC723.1 PC724.1 PC725.1 PC865.1 PC866.1 PC867.1 PC868.1 PC869.1 PC870.1 PC871.1 PC872.1 PC1003.1 PC1004.1 PC1005.1 PR403.1 PR404.1 ; also on sheet 15 45 97 104 105 106 107 120 129
PVDDQ_GH_VIN: PC677.1 PL46.2 PTC8.1 ; also on sheet 14 15 16
PVDDQ_GH_VSENN_R: PR405.2 ; also on sheet 16
PVDDQ_GH_VSENP_R: PR404.2 ; also on sheet 16
FM_CPU0_BDX_PRSNT_LVT3_N: PQ11.G PR433.2 ; also on sheet 51 139 179
FM_VCC_MAIN_EN: PR432.2 PR434.2 PR438.1 ; also on sheet 51
FM_VPP_MEM_EFGH_EN: PR409.1 ; also on sheet 17 51
PVPP_GH: PC734.1 PC737.1 PC738.1 PC739.1 PC740.1 PC741.1 PC742.1 PC743.1 PC744.1 PD25.K(CATHODE) PL36.2(F) PR410.1 ; also on sheet 104 105 106 107 160
PVPP_GH_EN: PC1047.2 PR409.2 PU36.2(EN)
PVPP_GH_LL: PC732.2 PC733.1 PL36.1(S) PR411.1 PU36.6(LL#6) PU36.7(LL#7) PU36.8(LL#8) PU36.9(LL#9) PU36.10(LL#10) PU36.11(LL#11)
PVPP_GH_LL_R: PC734.2 PC736.1 PR411.2
PVPP_GH_MODE: PR412.1 PR414.2 PU36.20(MODE)
PVPP_GH_PWRGD: PR412.2 PR646.2 PU36.3(PGOOD) ; also on sheet 16
PVPP_GH_RF: PR416.2 PR418.2 PU36.22(RF)
PVPP_GH_ROVP: PR804.1 PU36.5(ROVP)
PVPP_GH_SNB: PC733.2 PR413.1
PVPP_GH_TRIP: PR415.2 PU36.21(TRIP)
PVPP_GH_VBST: PR407.1 PU36.4(VBST)
PVPP_GH_VBST_RC: PC732.1 PR407.2
PVPP_GH_VDD: PC731.1 PR406.2 PU36.19(VDD)
PVPP_GH_VFB: PC736.2 PR417.1 PR419.1 PU36.1(VFB)
PVPP_GH_VFB_R: PR410.2 PR417.2
PVPP_GH_VIN: PC726.1 PC727.1 PC728.1 PC729.1 PC730.1 PL35.2 PU36.12(VIN) PU36.13(VIN) PU36.14(VIN) PU36.15(VIN) PU36.16(VIN) PU36.17(VIN)
PVPP_GH_VREG: PC735.2 PR416.1 PU36.18(VREG)
PWRGD_P1V5_PCH: PR570.2 ; also on sheet 8 51
PWRGD_P1V05_PCH: PR334.2 PR437.1 PR532.2 PU53.3(PGOOD) ; also on sheet 51
PWRGD_PVCCIO: PR427.1 PR429.1 PR570.1 PU37.5(PG)

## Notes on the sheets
sheet 10
- Power rail : P1V05_PCH
  Controller : TPS53318 (Fswitching=750KHz)
  TDC : 5A
  MAX :5.8A
  OCP :8A
- Input-Cap RMS Current = 1.61A
- I_rated=6A
  DCR=20mohm
  Z=22ohm
- Cyntec PCMB065T-R68
  L=0.68uH, DCR=3.9m ohm,
  Idc1=18A, Idc2=16A
  7.05*6.6*4.8 mm3
- FCCM Mode
- SS=8ms
- based on measure result
  change to 470pF and 10K ohm
  Aston 2015/03/30
- OCP =8A
- FS=750KHz
- based on Intel PDG 789 page
  modify it
  ASton 2015/03/25
- VFB=0.6V
  Vout=0.6X(1+7.34/10)=1.0404V
- change to 750k hz
  Aston 2015/3/30
- FAB1 REV006 20150324
- reomte sense path
  close PCH
sheet 11
- Power rail : PVCCIO(1V05/0V95)
  Controller : TPS53511 (Fswitching=700KHz)
  TDC :0.5A
  MAX :1A
  OCP :2.05A
- Input-Cap RMS Current = 0.28A
- FAB1 REV010 20150331
- change to 1000pF to improve body plot
  Aston 2015/3/31
- TDK SPM6530T-4R7M
  L=4.7uH, DCR=35.8m ohm,
  Idc1=6.2A, Idc2=5.6A
  7.1*6.5*3 mm3
- FAB1 REV010 20150331
- FS=700KHz
- SS=1.4ms
- PG POP
  Aston 18/04/14
- L: Vout=0.765x[1+2.43K/10K]
  =0.951
- H: Vout=0.765x[1+2.43K/(10K//18.7K)]
  =1.05
- FAB1 REV019 20150422
- Change to 84.27002.N31
sheet 12
- Power rail : PVPP_GH(2V5)
  Controller : TPS53318 (Fswitching=500KHz)
  TDC : 3.24A
  MAX : 6.6A
  OCP : 8.5A
- I_rated=6A
  DCR=20mohm
  Z=22ohm
- TDK SPM6530T-2R2M
  L=2.2uH, DCR=17.3 mohm,
- FCCM Mode
- SS=5.6ms
- OCP = 8.5A
- FS=500KHz
- Vout=0.6x(1+Ru/Rd)
sheet 13
- PVDDQ_GH Decoupling
- PVDDQ_GH LC Filter
- Place Capcitors Under Output Inductors on Bottom Side
- Place After Lout
- Place in CPU Socket Cavity
- Routed As Differential Pair
- Memory Slot Capacitors
